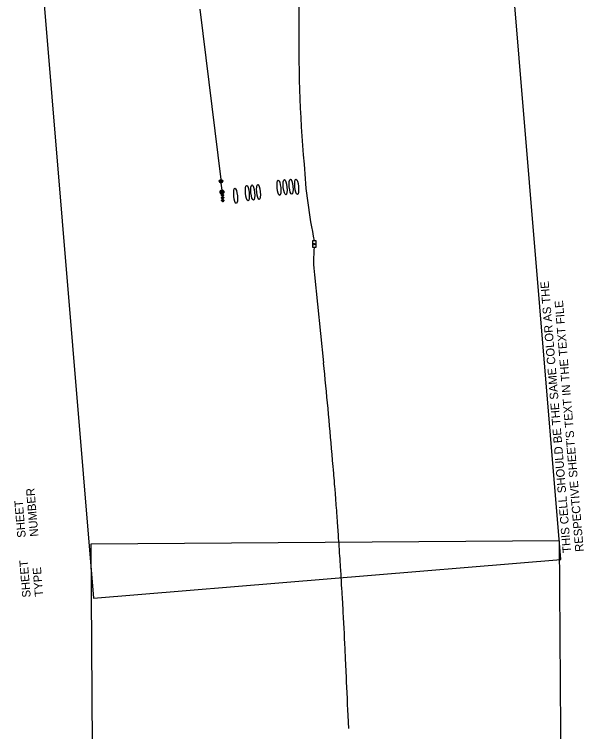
# Model space of a CAD drawing. Extents: x 601462 to 605493, y 331960 to 402715.
# Drawn here: x 602326 to 603509, y 363361 to 364853 of the extents above; entities that cross this region are included whole.
import ezdxf

# ---------------------------------------------------------------- set-up
doc = ezdxf.new("R2010")
doc.units = 0
for name, color, linetype in [('P_FTMS', 7, 'Continuous'), ('P_FTMSConduit', 7, 'Continuous'), ('P_MISC_TXT_1A (Construction)', 7, 'Continuous'), ('P_MISC_TXT_1B (Construction)', 7, 'Continuous')]:
    doc.layers.add(name, color=color, linetype=linetype)

# ---------------------------------------------------------------- blocks, each defined once
blk = doc.blocks.new('FTMS_FCV')
at = {"layer": 'P_FTMS'}
blk.add_line((12.7, 16.3), (0.6, -21.9), dxfattribs=at)
blk.add_lwpolyline([(39.1, 24.4), (-39.1, 24.4), (-39.1, -24.4), (39.1, -24.4)], close=True, dxfattribs=at)
blk.add_lwpolyline([(-12.1, 16.2), (0.6, -21.9)], dxfattribs=at)

msp = doc.modelspace()

# ---------------------------------------------------------------- linework, layer by layer
at = {"layer": 'P_FTMS'}
for p, q in [((602753.5, 364483.4), (602753.8, 364485.5)), ((602753.5, 364484.7), (602761.4, 364483.6)), ((602753.5, 364484.5), (602761.4, 364483.4)), ((602753.5, 364484.2), (602761.4, 364483.2)), ((602753.5, 364484), (602761.3, 364482.9)), ((602753.5, 364483.8), (602761.2, 364482.7)), ((602753.5, 364483.5), (602761.2, 364482.5)), ((602753.5, 364483.3), (602761.1, 364482.2)), ((602753.6, 364482.7), (602754.1, 364486.1)), ((602753.6, 364485), (602761.4, 364483.9)), ((602753.6, 364483), (602760.9, 364482)), ((602753.6, 364482.8), (602760.8, 364481.8)), ((602753.7, 364485.4), (602761.4, 364484.4)), ((602753.7, 364485.2), (602761.4, 364484.1)), ((602753.7, 364482.5), (602760.6, 364481.6)), ((602753.8, 364482.3), (602754.4, 364486.5)), ((602753.8, 364485.6), (602761.4, 364484.6)), ((602753.8, 364482.3), (602760.5, 364481.3)), ((602754, 364481.9), (602754.7, 364486.8)), ((602754, 364485.9), (602761.3, 364484.9)), ((602754, 364482), (602760.3, 364481.1)), ((602754.1, 364486.1), (602761.3, 364485.1)), ((602754.1, 364481.7), (602760.1, 364480.9)), ((602754.2, 364481.6), (602755, 364487.1)), ((602754.2, 364486.3), (602761.2, 364485.4)), ((602754.3, 364481.5), (602759.8, 364480.7)), ((602754.4, 364481.3), (602755.2, 364487.3)), ((602754.4, 364486.5), (602761.1, 364485.6)), ((602754.6, 364481.1), (602755.5, 364487.4)), ((602754.6, 364486.7), (602760.9, 364485.9)), ((602754.6, 364481.2), (602759.5, 364480.5)), ((602754.8, 364487), (602760.8, 364486.1)), ((602754.9, 364480.9), (602755.8, 364487.6)), ((602754.9, 364480.9), (602759.1, 364480.3)), ((602755.1, 364480.7), (602756, 364487.7)), ((602755.1, 364487.2), (602760.6, 364486.4)), ((602755.3, 364480.6), (602756.3, 364487.8)), ((602755.3, 364480.6), (602758.7, 364480.1)), ((602755.4, 364487.4), (602760.3, 364486.7)), ((602761, 364477.6), (602755.4, 364477.3)), ((602755.5, 364480.4), (602756.5, 364487.8)), ((602755.5, 364477.4), (602755.5, 364477.2)), ((602760.8, 364477.8), (602755.6, 364477.6)), ((602760.8, 364477.3), (602755.6, 364477.1)), ((602755.7, 364480.3), (602756.8, 364487.9)), ((602755.7, 364477.7), (602755.8, 364476.9)), ((602755.8, 364487.6), (602760, 364487)), ((602760.5, 364478), (602755.8, 364477.8)), ((602755.9, 364480.3), (602758, 364480)), ((602760.6, 364477.1), (602755.9, 364476.8)), ((602756, 364480.2), (602757, 364487.9)), ((602756, 364478), (602756, 364476.7)), ((602760.3, 364478.3), (602756.1, 364478.1)), ((602760.4, 364476.8), (602756.1, 364476.6)), ((602756.2, 364480.1), (602757.3, 364487.9)), ((602756.2, 364487.7), (602759.7, 364487.3)), ((602756.2, 364478.2), (602756.3, 364476.5)), ((602760, 364478.5), (602756.3, 364478.3)), ((602756.4, 364480.1), (602757.5, 364487.9)), ((602756.4, 364478.5), (602756.5, 364476.3)), ((602760.1, 364476.6), (602756.4, 364476.4)), ((602759.8, 364478.7), (602756.5, 364478.6)), ((602759.9, 364476.3), (602756.6, 364476.2)), ((602756.7, 364480), (602757.7, 364487.9)), ((602756.7, 364478.7), (602756.8, 364476)), ((602759.5, 364479), (602756.8, 364478.8)), ((602756.9, 364487.9), (602759.1, 364487.6)), ((602756.9, 364480), (602758, 364487.9)), ((602756.9, 364479), (602757, 364475.8)), ((602759.7, 364476.1), (602756.9, 364475.9)), ((602759.3, 364479.2), (602757, 364479.1)), ((602757.1, 364480), (602758.2, 364487.9)), ((602757.1, 364479.2), (602757.3, 364475.6)), ((602759.4, 364475.8), (602757.1, 364475.7)), ((602759, 364479.4), (602757.2, 364479.3)), ((602757.3, 364479.5), (602757.5, 364475.4)), ((602757.4, 364479.9), (602758.5, 364487.8)), ((602758.8, 364479.6), (602757.4, 364479.6)), ((602759.2, 364475.6), (602757.4, 364475.5)), ((602757.6, 364480), (602758.7, 364487.7)), ((602757.6, 364479.7), (602757.8, 364475.1)), ((602758.5, 364479.9), (602757.7, 364479.8)), ((602759, 364475.3), (602757.7, 364475.3)), ((602757.8, 364480), (602758, 364474.9)), ((602757.9, 364480), (602758.9, 364487.6)), ((602758.3, 364480.1), (602757.9, 364480.1)), ((602758, 364480.2), (602758.3, 364474.7)), ((602758.1, 364480), (602759.2, 364487.5)), ((602758.3, 364480.1), (602758.5, 364474.8)), ((602758.4, 364480.1), (602759.4, 364487.4)), ((602758.5, 364479.9), (602758.8, 364475.1)), ((602758.6, 364480.1), (602759.6, 364487.3)), ((602758.8, 364479.6), (602759, 364475.3)), ((602758.9, 364480.2), (602759.8, 364487.1)), ((602759, 364479.4), (602759.2, 364475.6)), ((602759.1, 364480.3), (602760, 364487)), ((602759.3, 364479.2), (602759.4, 364475.8)), ((602759.4, 364480.4), (602760.3, 364486.8)), ((602759.5, 364479), (602759.7, 364476.1)), ((602759.7, 364480.6), (602760.5, 364486.5)), ((602759.8, 364478.7), (602759.9, 364476.3)), ((602759.9, 364480.8), (602760.7, 364486.3)), ((602760, 364478.5), (602760.1, 364476.6)), ((602760.2, 364481.1), (602760.9, 364486)), ((602760.3, 364478.3), (602760.4, 364476.8)), ((602760.5, 364481.3), (602761.1, 364485.6)), ((602760.5, 364478), (602760.6, 364477.1)), ((602760.8, 364481.7), (602761.2, 364485.2)), ((602760.8, 364477.8), (602760.8, 364477.3)), ((602761.1, 364482.3), (602761.4, 364484.5)), ((602761.3, 364472), (602755.7, 364471.7)), ((602755.8, 364471.8), (602755.8, 364471.6)), ((602761.1, 364472.2), (602755.9, 364471.9)), ((602761.1, 364471.7), (602755.9, 364471.5)), ((602756, 364472.1), (602756.1, 364471.3)), ((602761.6, 364466.4), (602756, 364466.1)), ((602760.8, 364472.4), (602756.1, 364472.2)), ((602756.1, 364466.2), (602756.1, 364465.9)), ((602760.9, 364471.5), (602756.2, 364471.2)), ((602761.4, 364466.6), (602756.2, 364466.3)), ((602761.4, 364466.1), (602756.2, 364465.8)), ((602756.3, 364472.3), (602756.3, 364471.1)), ((602756.3, 364466.5), (602756.4, 364465.7)), ((602760.6, 364472.7), (602756.4, 364472.4)), ((602760.7, 364471.2), (602756.4, 364471)), ((602761.1, 364466.8), (602756.4, 364466.6)), ((602756.5, 364472.6), (602756.6, 364470.9)), ((602761.2, 364465.8), (602756.5, 364465.6)), ((602760.3, 364472.9), (602756.6, 364472.7)), ((602756.6, 364466.7), (602756.6, 364465.5)), ((602756.7, 364472.8), (602756.8, 364470.6)), ((602760.4, 364471), (602756.7, 364470.8)), ((602760.9, 364467), (602756.7, 364466.8)), ((602761, 364465.6), (602756.7, 364465.4)), ((602760.1, 364473.1), (602756.8, 364472.9)), ((602756.8, 364467), (602756.9, 364465.3)), ((602760.2, 364470.7), (602756.9, 364470.5)), ((602760.6, 364467.3), (602756.9, 364467.1)), ((602757, 364473.1), (602757.1, 364470.4)), ((602757, 364467.2), (602757.1, 364465)), ((602760.7, 364465.3), (602757, 364465.2)), ((602759.8, 364473.3), (602757.1, 364473.2)), ((602760.4, 364467.5), (602757.1, 364467.3)), ((602757.2, 364473.3), (602757.3, 364470.2)), ((602760, 364470.5), (602757.2, 364470.3)), ((602760.5, 364465.1), (602757.2, 364464.9)), ((602759.6, 364473.6), (602757.3, 364473.4)), ((602760.1, 364467.7), (602757.3, 364467.6)), ((602757.3, 364467.5), (602757.4, 364464.8)), ((602757.4, 364473.6), (602757.6, 364470)), ((602759.7, 364470.2), (602757.4, 364470.1)), ((602759.3, 364473.8), (602757.5, 364473.7)), ((602757.5, 364467.7), (602757.6, 364464.6)), ((602760.3, 364464.8), (602757.5, 364464.7)), ((602757.6, 364473.8), (602757.8, 364469.7)), ((602759.9, 364467.9), (602757.6, 364467.8)), ((602759.1, 364474), (602757.7, 364474)), ((602759.5, 364470), (602757.7, 364469.9)), ((602757.7, 364468), (602757.9, 364464.3)), ((602760, 364464.6), (602757.7, 364464.5)), ((602759.6, 364468.2), (602757.8, 364468.1)), ((602758.8, 364475.1), (602757.9, 364475)), ((602757.9, 364474.1), (602758.1, 364469.5)), ((602757.9, 364468.2), (602758.1, 364464.1)), ((602758.8, 364474.2), (602758, 364474.2)), ((602759.3, 364469.7), (602758, 364469.6)), ((602759.4, 364468.4), (602758, 364468.3)), ((602759.8, 364464.3), (602758, 364464.2)), ((602758.1, 364474.3), (602758.3, 364469.3)), ((602758.5, 364474.8), (602758.2, 364474.8)), ((602758.6, 364474.5), (602758.2, 364474.5)), ((602759.1, 364469.5), (602758.2, 364469.4)), ((602758.2, 364468.5), (602758.4, 364463.9)), ((602759.6, 364464.1), (602758.2, 364464)), ((602758.3, 364474.6), (602758.6, 364469.1)), ((602759.1, 364468.6), (602758.3, 364468.6)), ((602758.4, 364468.7), (602758.6, 364463.7)), ((602758.8, 364469.2), (602758.5, 364469.2)), ((602758.8, 364469.2), (602758.5, 364469.2)), ((602758.9, 364468.9), (602758.5, 364468.8)), ((602759.4, 364463.8), (602758.5, 364463.8)), ((602758.6, 364474.5), (602758.8, 364469.2)), ((602758.6, 364469), (602758.9, 364463.4)), ((602758.8, 364474.2), (602759.1, 364469.5)), ((602759.1, 364463.6), (602758.8, 364463.6)), ((602758.9, 364468.9), (602759.1, 364463.6)), ((602759.1, 364474), (602759.3, 364469.7)), ((602759.1, 364468.6), (602759.4, 364463.8)), ((602759.3, 364473.8), (602759.5, 364470)), ((602759.4, 364468.4), (602759.6, 364464.1)), ((602759.6, 364473.6), (602759.7, 364470.2)), ((602759.6, 364468.2), (602759.8, 364464.3)), ((602759.8, 364473.3), (602760, 364470.5)), ((602759.9, 364467.9), (602760, 364464.6)), ((602760.1, 364473.1), (602760.2, 364470.7)), ((602760.1, 364467.7), (602760.3, 364464.8)), ((602760.3, 364472.9), (602760.4, 364471)), ((602760.4, 364467.5), (602760.5, 364465.1)), ((602760.6, 364472.7), (602760.7, 364471.2)), ((602760.6, 364467.3), (602760.7, 364465.3)), ((602760.8, 364472.4), (602760.9, 364471.5)), ((602760.9, 364467), (602761, 364465.6)), ((602761.1, 364472.2), (602761.1, 364471.7)), ((602761.1, 364466.8), (602761.2, 364465.8)), ((602761.4, 364466.6), (602761.4, 364466.1))]:
    msp.add_line(p, q, dxfattribs=at)
for points in [[(602758.4, 364474.6), (602755.4, 364477.3), (602758.1, 364480.3), (602761, 364477.6)], [(602758.7, 364469), (602755.7, 364471.7), (602758.4, 364474.7), (602761.3, 364472)], [(602759, 364463.4), (602756, 364466.1), (602758.7, 364469), (602761.6, 364466.4)]]:
    msp.add_lwpolyline(points, close=True, dxfattribs=at)
for centre, radius in [((602755.4, 364506.1), 3.75), ((602757.4, 364483.9), 4)]:
    msp.add_circle(centre, radius, dxfattribs=at)
for centre, start, end in [((602755.2, 364501.6), 34.9369, 141.1925), ((602755.5, 364510.6), 214.9369, 321.1925)]:
    msp.add_arc(centre, 3.75, start, end, dxfattribs=at)
for centre in [(602875.9, 364492.6), (602888.7, 364493.8), (602901.1, 364495), (602912.7, 364494.7), (602785.8, 364475.7), (602810.1, 364481.6), (602821.4, 364482.7), (602833.4, 364483.9)]:
    msp.add_ellipse(centre, major_axis=(1.5, -15.9), ratio=0.23471, dxfattribs=at)
at = {"layer": 'P_FTMSConduit'}
for p, q in [((602711.6, 364864.5), (602754.9, 364509.8)), ((602757.7, 364487.9), (602755.9, 364502.3))]:
    msp.add_line(p, q, dxfattribs=at)
for points in [[(602949.8, 364311.2), (602968.6, 364128.6)], [(603021.4, 363367.6), (603019.6, 363394.7), (603019.2, 363406.6), (603018.7, 363417.6), (603018.3, 363429.4), (603017.6, 363442.7), (603017.3, 363453.3), (603016.6, 363465.1), (603016.4, 363473.5), (603015.6, 363486.7), (603015.5, 363491.7), (603015.2, 363495.5), (603014.8, 363503.3), (603014.5, 363510.2), (603014, 363520.6), (603013.8, 363525.8), (603013.5, 363531.7), (603013.3, 363536.7), (603013.1, 363541), (603012.9, 363543.3), (603012.7, 363547.5), (603012.4, 363552), (603012.3, 363557.4), (603011.9, 363565.8), (603011.4, 363575.6), (603010.4, 363598.6), (603009.6, 363609.8), (603009.2, 363618.7), (603008.9, 363623.3), (603008.4, 363631.3), (603008.1, 363636.4), (603007.9, 363640.5), (603007.4, 363647.3), (603007.2, 363651.7), (603006.7, 363659.5), (603006.3, 363666.2), (603006.1, 363671.3), (603005.8, 363675.9), (603005.6, 363682), (603005.2, 363687.7), (603004.5, 363697.1), (603004.1, 363703.9), (603003.7, 363709.2), (603003.2, 363714.8), (603002.9, 363720.7), (603002.5, 363727.2), (603002.1, 363732.5), (603001.7, 363738.1), (603001.5, 363741.3), (603001.3, 363745.6), (603000.8, 363752.4), (603000.6, 363757.2), (603000, 363764.5), (602999.5, 363771.8), (602999.2, 363776.9), (602998.8, 363781.9), (602998.6, 363785), (602998.2, 363789.7), (602997.8, 363794.6), (602997.4, 363800.3), (602997, 363806.2), (602996.7, 363811.2), (602996.5, 363814.4), (602996.2, 363820.9), (602995.5, 363827.4), (602995.2, 363831.9), (602995, 363836.5), (602994.5, 363842.2), (602994, 363848.3), (602993.6, 363853), (602993.3, 363858.6), (602992.9, 363862.6), (602992.6, 363866.9), (602992.3, 363870.1), (602991.6, 363877.5), (602991.1, 363883.3), (602990.6, 363889.4), (602990.3, 363893.9), (602990, 363898.2), (602989.3, 363905.8), (602988.7, 363912.8), (602988.2, 363918.8), (602987.6, 363925.5), (602987.4, 363929), (602986.9, 363935.1), (602986.6, 363938)]]:
    msp.add_lwpolyline(points, dxfattribs=at)
for centre, radius, start, end in [((605889.6, 364848.5), 2972.1, 175.3176, 179.9052), ((605926.8, 364799.6), 3009.8, 178.975, 184.9191), ((603971.2, 364599.5), 1044.7, 183.1829, 192.0156), ((603197.9, 364342.1), 250, 173.7812, 187.0987), ((591459.8, 362945.4), 11569.4, 4.92166, 5.86941)]:
    msp.add_arc(centre, radius, start, end, dxfattribs=at)
at = {"layer": 'P_MISC_TXT_1A (Construction)'}
msp.add_lwpolyline([(603462, 363719.1), (603332, 365288.8), (602360.3, 365208.3), (602490.3, 363638.7)], close=True, dxfattribs=at)
at = {"layer": 'P_MISC_TXT_1B (Construction)'}
msp.add_lwpolyline([(603470.1, 362182.9), (603459.3, 363757.9), (602484.4, 363751.2), (602495.1, 362176.2)], close=True, dxfattribs=at)

# ---------------------------------------------------------------- block references
at = {"layer": 'P_FTMS', "xscale": 0.16404166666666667, "yscale": 0.16404166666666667, "rotation": 90.21124366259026}
msp.add_blockref('FTMS_FCV', (602949.4, 364375.6), dxfattribs=at)

# ---------------------------------------------------------------- texts
at = {"layer": 'P_MISC_TXT_1A (Construction)'}
for s, p in [('THIS CELL SHOULD BE THE SAME COLOR AS THE', (603483.5, 363733.9)), ("RESPECTIVE SHEET'S TEXT IN THE TEXT FILE", (603509.7, 363736.1)), ('NUMBER', (602375.7, 363767.6)), ('SHEET', (602349.5, 363765.4)), ('SHEET', (602359.8, 363640.9)), ('TYPE', (602386, 363643))]:
    msp.add_text(s, height=17.5, rotation=94.7345, dxfattribs=at).set_placement(p)

doc.saveas('drawing.dxf')
